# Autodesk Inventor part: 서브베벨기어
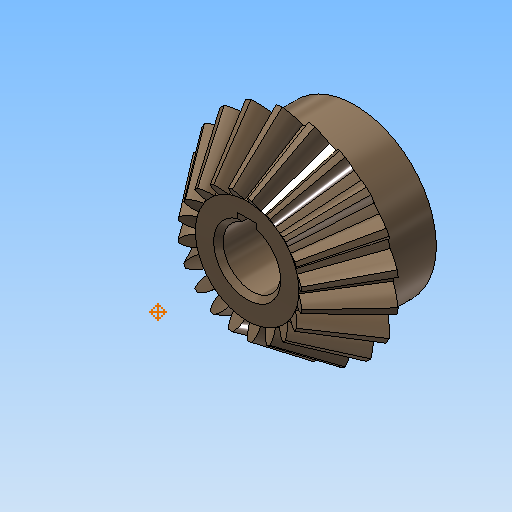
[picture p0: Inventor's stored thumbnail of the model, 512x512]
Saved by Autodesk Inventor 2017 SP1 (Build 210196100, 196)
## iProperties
Created: 2018-09
Part Number: 서브베벨기어
Material: 강철, 탄소
Document SubType Name: Modeling
Categories: <?xml version="1.0" encoding="UTF-16"?> <MemberInstance><Categories><FamilyTemplate><FamilyTemplateParameter ValueType="xs:double" Id="1" ObjectReferenceKey="da
Mass: 135.037 g
Surface Area: 63.6444 cm^2
Volume: 17.1585 cm^3
Density: 7.87 g/cm^3
Appearance: 얼룩무늬
CustomPartVersion: 1
d48: 0.000 mm
d49: 0.000 mm
d50: 90.00 deg
d52: 0.000 mm
d53: 0.000 mm
d54: 0.00 deg
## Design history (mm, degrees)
node "맨 위 점"
node "메쉬 평면2"
sketch "톱니 본체 스케치"
  geometry: L1 (0, 0)-(18.003, -31.331); L2 (18.003, -31.331)-(21.664, -28.891); L3 (21.664, -28.891)-(0, 0); L4 (20, -30)-(0, 0); L5 (10.813, -18.818)-(13.012, -17.352); L6 (18.003, -31.331)-(10.813, -18.818); L7 (21.664, -28.891)-(13.012, -17.352); L8 (0, -39.387)-(0, 6.564) reference; L9 (0, -30)-(21.664, -30)
  constraints: 16 end point, 4 point on line, 3 perpendicular, 2 collinear, 1 horizontal alignment, 1 vertical alignment
  dimensions: "d0" = 40 diameter of L4.start L8 (= da_de); "d1" = 36.00616 diameter of L1.end L8 (= da_dfe); "d2" = 43.3282 diameter of L2.end L8 (= da_dae); "d3" = 14.4 distance between parallel lines of L2 L5 (= da_b); "d4" = 28.8906 vertical distance of L2.end L1.start (= da_ve)
revolve "톱니 본체" sketch "톱니 본체 스케치" stored, may be unused: angle "d5" = 90 deg
node "시작점"
node "톱니 평면"
sketch "시작 스케치"
  geometry: L1 (0, -23.505)-(0, 10.645) reference; L2 (-0.834, -2.928)-(0.834, -2.928); A1 r 8.898 centre (-9.698, -3.713) between (-0.834, -2.928) and (-3.903, 3.04); A2 r 8.898 centre (9.698, -3.713) between (3.903, 3.04) and (0.834, -2.928); A3 r 27.357 centre (0, -24.037) between (3.903, 3.04) and (-3.903, 3.04); 1 further point
  constraints: 6 point on circle, 3 centre point, 3 symmetric about line, 2 end point, 1 coincident, 1 perpendicular, 1 other
  dimensions: "d7" = 8.89846 radius of A1 (= fd_rr); "d8" = 9.69794 horizontal distance of point (0, -24.037) A1.centre (= fd_x); "d9" = 20.32439 vertical distance of point (0, -24.037) A1.centre (= fd_y); "d57" = 27.35701 radius of A3 (= 0.5 x fd_dva + 0.3 x da_he); "d58" = 21.10901 distance from line of A3.centre L2 (= 0.5 x fd_dva - 1.12 x da_he)
node "끝점"
  node "끝 평면"
sketch "3D 스케치 오른쪽"
  node "Helical Curve Right" dims "d65" = 229.90621 (computed from da_dm, da_delta, da_beta), "d66" = 31.5, "d67" = 40 (= da_de), "d68" = -5.88003 (= -da_delta), "d69" = 12.16458 (computed from fd_loft, da_delta)
node "끝 평면 오른쪽"
sketch "끝 스케치 오른쪽"
  geometry: L1 (0, -22.649)-(0, 12.15) reference; L2 (-0.497, -1.72)-(0.497, -1.72); A1 r 5.299 centre (-5.775, -2.187) between (-0.497, -1.72) and (-2.324, 1.834); A2 r 5.299 centre (5.775, -2.187) between (2.324, 1.834) and (0.497, -1.72); A3 r 16.291 centre (0, -14.29) between (2.324, 1.834) and (-2.324, 1.834); 1 further point
  constraints: 6 point on circle, 3 centre point, 3 symmetric about line, 2 end point, 1 coincident, 1 perpendicular, 1 other
  dimensions: "d70" = 5.77526 horizontal distance of A3.centre A1.centre (computed from fd_x, fd_ratio); "d71" = 12.10346 vertical distance of point (0, -14.29) A1.centre (computed from fd_y, fd_ratio); "d72" = 5.29916 radius of A1 (computed from fd_rr, fd_ratio); "d73" = 12.57071 distance from line of point (0, -14.29) L2 (computed from d58, fd_ratio); "d74" = 16.29149 radius of A3 (computed from d57, fd_ratio)
feature "로프트 오른쪽" sketch "끝 스케치 오른쪽" dims "d75" = 0, "d77" = 0, "d79" = 0, "d80" = 90 deg, "d85" = 20, "d92" = 90 deg, "d93" = 90 deg, "da_teethtype" = 0 [user parameter]
sketch "3D 스케치 왼쪽"
  node "Helical Curve Left" dims "d26" = 229.90621 (computed from da_dm, da_delta, da_beta), "d27" = 12.16458 (computed from fd_loft, da_delta), "d28" = 40 (= da_de), "d29" = -5.88003 (= -da_delta)
node "끝 평면 왼쪽"
sketch "끝 스케치 왼쪽" dims "d56" = 10.82768 (derived)
  geometry: L1 (0, -35.087)-(0, 18.089) reference; L2 (-0.497, -1.716)-(0.497, -1.716); A1 r 5.299 centre (-5.775, -2.183) between (-0.497, -1.716) and (-2.324, 1.838); A2 r 5.299 centre (5.775, -2.183) between (2.324, 1.838) and (0.497, -1.716); A3 r 16.291 centre (0, -14.287) between (2.324, 1.838) and (-2.324, 1.838); 2 further points; 1 other entity
  constraints: 6 point on circle, 3 centre point, 3 symmetric about line, 2 end point, 1 coincident, 2 other
  dimensions: "d30" = 5.29916 radius of A1 (computed from fd_rr, fd_ratio); "d31" = 5.77526 horizontal distance of point (0, -14.287) A1.centre (computed from fd_x, fd_ratio); "d32" = 12.10346 vertical distance of A1.centre point (0, -14.287) (computed from fd_y, fd_ratio); "d61" = 16.29149 radius of A3 (computed from d57, fd_ratio); "d62" = 12.57071 distance from line of point (0, -14.287) L2 (computed from d58, fd_ratio)
feature "로프트 왼쪽" sketch "끝 스케치 왼쪽" dims "d35" = 0, "d37" = 0, "d39" = 0, "d40" = 90 deg, "d84" = 10, "d90" = 90 deg, "d91" = 90 deg, "da_teethtype" = 0 [user parameter]
sketch "본체 스케치"
  geometry: L1 (0, -35.038)-(0, -19.531) reference; L2 (18.003, -31.331)-(10.813, -18.818) reference; L3 (10.813, -18.818)-(0, -18.818); L4 (18.003, -31.331)-(0, -31.331)
  constraints: 4 end point, 2 perpendicular, 2 point on line
revolve "본체 고정" sketch "본체 스케치" stored, may be unused: angle "d46" = 90 deg
feature "피치 지름" dims angle "d47" = 90 deg
sketch "스케치8"
  geometry: C1 r 17 at (0, 0); 1 further point
  constraints: 1 centre point, 1 coincident
  dimensions: "d94" = 34 diameter of C1
extrude "돌출1" join sketch "스케치8" distance "d95" = 10; taper "d96" = 0 deg
sketch "스케치9"
  geometry: 1 further point
hole "구멍1" sketch "스케치9" at (0, 0) diameter "d97" = 12; stored, may be unused: countersink angle "d101" = 90 deg, drill point angle "d103" = 118 deg; dims "d98" = 6, "d99" = 4, "d100" = 2, "d102" = 8
sketch "스케치10"
  geometry: 1 further point
sketch "스케치11"
  geometry: 1 further point
sketch "스케치12"
  geometry: L1 (-2, 5.657)-(-2, 7.8); L2 (-2, 7.8)-(2, 7.8); L3 (2, 7.8)-(2, 5.657); A1 r 6 centre (0, 0) between (-2, 5.657) and (2, 5.657) reference; 1 further point
  constraints: 6 end point, 2 parallel, 2 point on circle, 1 perpendicular, 1 vertical
  dimensions: "d104" = 4 distance of L1.end L2.end; "d105" = 13.8 dimension on A1 L2
extrude "돌출2" cut sketch "스케치12" stored distance "d106" = 7; taper "d107" = 0 deg
chamfer "모따기1" distance "d108" = 1; stored, may be unused: second distance "d109" = 2, angle "d110" = 45 deg
body "Solid1"
feature "로프트" dims "d17" = 0, "d18" = 90 deg, "d19" = 0, "d20" = 90 deg, "d89" = 0, "da_teethtype" = 0 [user parameter]
pattern_circular "원형 패턴" dims angle "d22" = 360 deg, "d88" = 0, "da_teethtype" = 0 [user parameter]
pattern_circular "원형 패턴 오른쪽" dims angle "d82" = 360 deg, "da_teethtype" = 0 [user parameter]
pattern_circular "원형 패턴 왼쪽" dims angle "d42" = 360 deg, "da_teethtype" = 0 [user parameter]
sketch "끝 스케치"
  geometry: L1 (0, -15.359)-(0, 6.983) reference; L2 (-0.497, -1.72)-(0.497, -1.72); A1 r 5.299 centre (-5.775, -2.187) between (-0.497, -1.72) and (-2.324, 1.834); A2 r 5.299 centre (5.775, -2.187) between (2.324, 1.834) and (0.497, -1.72); A3 r 16.291 centre (0, -14.29) between (2.324, 1.834) and (-2.324, 1.834); 1 further point
  constraints: 6 point on circle, 3 centre point, 3 symmetric about line, 2 end point, 1 coincident, 1 other
  dimensions: "d12" = 5.29916 radius of A1 (computed from fd_rr, fd_ratio); "d15" = 5.77526 horizontal distance of A1.centre point (0, -14.29) (computed from fd_x, fd_ratio); "d16" = 12.10346 vertical distance of A1.centre point (0, -14.29) (computed from fd_y, fd_ratio); "d59" = 16.29149 radius of A3 (computed from d57, fd_ratio); "d60" = 12.57071 distance from line of A3.centre L2 (computed from d58, fd_ratio)
sketch "Sketch6"
  geometry: L1 (20, -30)-(0, 0) reference; L2 (0, -37.8)-(0, 6.3) reference
body "Srf1"
other parameters: "da_b" = 14.4 [user parameter; used in 2 equation terms], "da_de" = 40 [user parameter; used in 4 equation terms], "da_dae" = 43.3282 [user parameter; used in 2 equation terms], "da_dfe" = 36.00616 [user parameter; used in 1 equation term], "da_le" = 36.05551 [user parameter; used in 1 equation term], "da_omega" = 90 deg [user parameter; used in 1 equation term], "da_beta" = 0 [user parameter; used in 2 equation terms], "da_delta" = 5.88003 [user parameter; used in 8 equation terms], "da_alpha" = 20 deg [user parameter; used in 2 equation terms], "da_he" = 4.4 [user parameter; used in 4 equation terms], "da_ve" = 28.8906 [user parameter; used in 1 equation term], "fd_dv" = 48.07402 (computed from da_de, da_delta) [user parameter; used in 1 equation term], "fd_dva" = 52.07402 (computed from da_dae, da_delta) [user parameter; used in 3 equation terms], "fd_dvb" = 45.1748 (computed from fd_dv, da_alpha) [user parameter; used in 2 equation terms], "da_zv" = 240.37008 [user parameter; used in 1 equation term], "fd_loft" = 14.62 (= da_b + 0.05 x da_he) [user parameter; used in 4 equation terms], "fd_ratio" = 5.95514 (computed from da_le, fd_loft) [user parameter; used in 15 equation terms], "fd_rr" = 8.89846 (computed from fd_dd, fd_dvb) [user parameter; used in 6 equation terms], "fd_angle" = 0.66075 (computed from da_zv) [user parameter; used in 4 equation terms], "fd_x1" = 1.58709 (computed from da_dvw, fd_angle) [user parameter; used in 1 equation term], "fd_y1" = 23.98456 (computed from da_dvw, fd_angle) [user parameter; used in 1 equation term], "fd_x2" = 8.11084 (computed from fd_rr, fd_angle2, fd_angle) [user parameter; used in 1 equation term], "fd_y2" = 3.66016 (computed from fd_rr, fd_angle2, fd_angle) [user parameter; used in 1 equation term], "fd_x" = 9.69794 (= fd_x1 + fd_x2) [user parameter; used in 4 equation terms], "fd_y" = 20.32439 (= fd_y1 - fd_y2) [user parameter; used in 4 equation terms], "fd_angle2" = 3.57832 (computed from fd_dvb, fd_dd, da_alpha) [user parameter; used in 2 equation terms], "fd_dd" = 48.55402 (= fd_dva - 0.8 x da_he) [user parameter; used in 2 equation terms], "da_dvw" = 48.07402 [user parameter; used in 2 equation terms], "d11" = 14.62 (= fd_loft), "da_dm" = 32.01232 [user parameter; used in 2 equation terms], "da_x" = 0 [user parameter], "da_m" = 2 [user parameter], "d48" = 0, "d49" = 0, "d50" = 90 deg (= da_omega), "d51" = 9 deg (computed from da_z), "d52" = 0, "d53" = 0, "d54" = 0 deg
